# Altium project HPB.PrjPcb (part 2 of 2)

## Sheet Faults.SchDoc: MARS2 LVPS - HPB - Fault Multiplexer
size 431 x 279 mm; Organization: ORGANIZATION; Address1: APPLIED PHYSICS LAB; Address2: UNIVERSITY OF WASHINGTON; Address3: 1013 NE 40TH STREET; Address4: SEATTLE, WA 98105; DocumentNumber: 11; Revision: -; SheetNumber: 13; SheetTotal: 15; ENG_APP_DATE: --/--/--; DSN_APP_DATE: --/--/--; CHK_APP_DATE: --/--/--
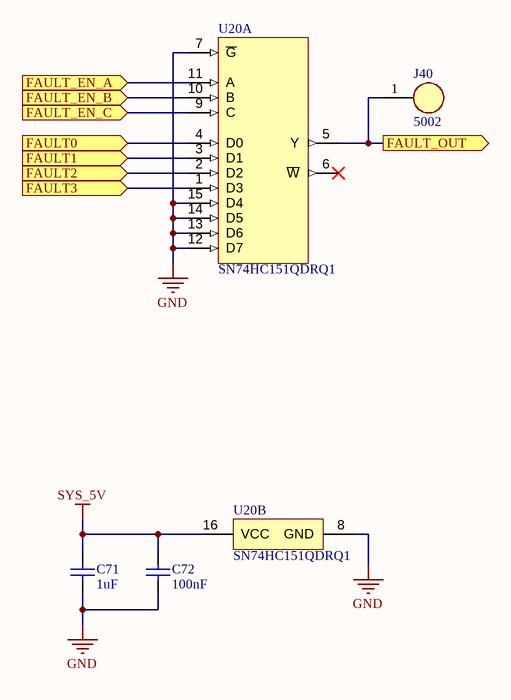
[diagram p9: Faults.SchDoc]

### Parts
C71  value 1uF  [CAPC3225X270X30ML30]  (hidden comment: Capacitor 1uF 10%, 50V, X7R, 1210)
C72  value 100nF  [CAPC1608X90X40NL10T20]  (hidden comment: Capacitor 100 nF +/-10% 50 V 0603)
J40  5002  [FP-5002-MFG]
U20  SN74HC151QDRQ1  [D0016A_M]  (parts A,B of 2)

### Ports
FAULT0 (in), FAULT1 (in), FAULT2 (in), FAULT3 (in), FAULT_EN_A (in), FAULT_EN_B (in), FAULT_EN_C (in), FAULT_OUT (out)

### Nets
GND: C71.1 C72.1 U20.7(~{G}) U20.8(GND) U20.12(D7) U20.13(D6) U20.14(D5) U20.15(D4)
SYS_5V: C71.2 C72.2 U20.16(VCC)  [project net VCC]
FAULT_MUX_A: U20.11(A) ; port FAULT_EN_A
FAULT_MUX_B: U20.10(B) ; port FAULT_EN_B
FAULT_MUX_C: U20.9(C) ; port FAULT_EN_C
FAULT_SENSE_HCB: J40.1 U20.5(Y) ; port FAULT_OUT
OUT: U20.1(D3) ; port FAULT3
OUT: U20.2(D2) ; port FAULT2  [a separate net that carries the same name]
OUT: U20.3(D1) ; port FAULT1  [a separate net that carries the same name]
OUT: U20.4(D0) ; port FAULT0  [a separate net that carries the same name]

Not connected (* = marked no-connect by the designer): U20 6(~{W})*

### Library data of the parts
C71 = CMP-001-00181-9: Chip Capacitor, 1uF, 10%, 50 V, X7R 1210 (3225 Metric); Capacitor Type: Ceramic
C72 = CMP-001-00017-14: Chip Capacitor, 100 nF, +/- 10%, 50 V, 0603 (1608 Metric); Voltage Rating: 50V; Capacitor Type: Ceramic
J40 = CMP-002-00083-3: TEST POINT PC MINI .040D WHITE; Body Material: Bronze
U20 = CMP-016-00018-2: Automotive 5-V, 8: 1 1-channel general-purpose multiplexer 16-SOIC -40 to 125; Max Supply Voltage: 6V; Bandwidth: 28MHz; Min Supply Voltage: 2V; Number of Output Lines: 1; Number of Input Lines: 8; High Level Output Current: 7.8mA; Logic Function: Multiplexer,Mux; Propagation Delay: 33ns

## Sheet Switches.SchDoc: MARS2 LVPS - HPB - PWR Switches
size 431 x 279 mm; Organization: ORGANIZATION; Address1: APPLIED PHYSICS LAB; Address2: UNIVERSITY OF WASHINGTON; Address3: 1013 NE 40TH STREET; Address4: SEATTLE, WA 98105; DocumentNumber: 8; Revision: -; SheetNumber: 9; SheetTotal: 15; ENG_APP_DATE: --/--/--; DSN_APP_DATE: --/--/--; CHK_APP_DATE: --/--/--
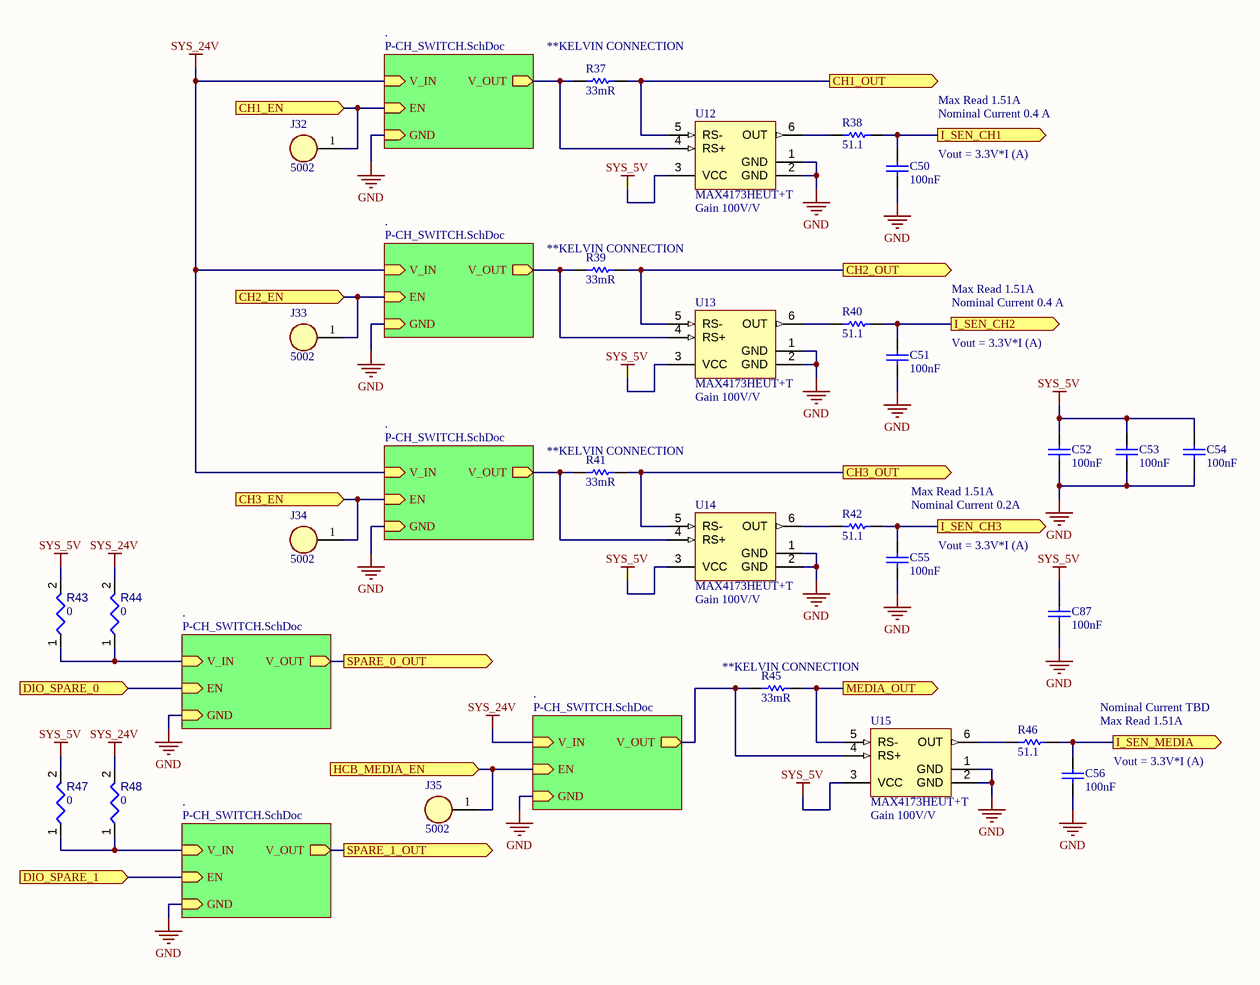
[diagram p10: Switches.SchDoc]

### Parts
C50  value 100nF  [CAPC1608X90X40NL10T20]  (hidden comment: Capacitor 100 nF +/-10% 50 V 0603)
C51  value 100nF  [CAPC1608X90X40NL10T20]  (hidden comment: Capacitor 100 nF +/-10% 50 V 0603)
C52  value 100nF  [CAPC1608X90X40NL10T20]  (hidden comment: Capacitor 100 nF +/-10% 50 V 0603)
C53  value 100nF  [CAPC1608X90X40NL10T20]  (hidden comment: Capacitor 100 nF +/-10% 50 V 0603)
C54  value 100nF  [CAPC1608X90X40NL10T20]  (hidden comment: Capacitor 100 nF +/-10% 50 V 0603)
C55  value 100nF  [CAPC1608X90X40NL10T20]  (hidden comment: Capacitor 100 nF +/-10% 50 V 0603)
C56  value 100nF  [CAPC1608X90X40NL10T20]  (hidden comment: Capacitor 100 nF +/-10% 50 V 0603)
C87  value 100nF  [CAPC1608X90X40NL10T20]  (hidden comment: Capacitor 100 nF +/-10% 50 V 0603)
J32  5002  [FP-5002-MFG]
J33  5002  [FP-5002-MFG]
J34  5002  [FP-5002-MFG]
J35  5002  [FP-5002-MFG]
R37  Resistance: 33mR  [RESC3216X70X50NL05T20]  (hidden comment: Resistor 0R033 1% 1206 1W)
R38  value 51.1  [RESC1609X50X30ML08T20]  (hidden comment: Resistor 51R1 +/-1% 0603 100 mW)
R39  Resistance: 33mR  [RESC3216X70X50NL05T20]  (hidden comment: Resistor 0R033 1% 1206 1W)
R40  value 51.1  [RESC1609X50X30ML08T20]  (hidden comment: Resistor 51R1 +/-1% 0603 100 mW)
R41  Resistance: 33mR  [RESC3216X70X50NL05T20]  (hidden comment: Resistor 0R033 1% 1206 1W)
R42  value 51.1  [RESC1609X50X30ML08T20]  (hidden comment: Resistor 51R1 +/-1% 0603 100 mW)
R43  value 0  [RESC0603(1608)_L]  (hidden comment: Jumper 0603)
R44  value 0  [RESC0603(1608)_L]  (hidden comment: Jumper 0603)
R45  Resistance: 33mR  [RESC3216X70X50NL05T20]  (hidden comment: Resistor 0R033 1% 1206 1W)
R46  value 51.1  [RESC1609X50X30ML08T20]  (hidden comment: Resistor 51R1 +/-1% 0603 100 mW)
R47  value 0  [RESC0603(1608)_L]  (hidden comment: Jumper 0603)
R48  value 0  [RESC0603(1608)_L]  (hidden comment: Jumper 0603)
U12  MAX4173HEUT+T  [MAXM-U6+1_N]
U13  MAX4173HEUT+T  [MAXM-U6+1_N]
U14  MAX4173HEUT+T  [MAXM-U6+1_N]
U15  MAX4173HEUT+T  [MAXM-U6+1_N]

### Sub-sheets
. = P-CH_SWITCH.SchDoc: V_OUT (out), V_IN (in), EN (in), GND (in)
. = P-CH_SWITCH.SchDoc: V_OUT (out), V_IN (in), EN (in), GND (in)
. = P-CH_SWITCH.SchDoc: V_OUT (out), V_IN (in), EN (in), GND (in)
. = P-CH_SWITCH.SchDoc: V_OUT (out), V_IN (in), EN (in), GND (in)
. = P-CH_SWITCH.SchDoc: V_OUT (out), V_IN (in), EN (in), GND (in)
. = P-CH_SWITCH.SchDoc: V_OUT (out), V_IN (in), EN (in), GND (in)

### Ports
CH1_EN (in), CH1_OUT (out), CH2_EN (in), CH2_OUT (out), CH3_EN (in), CH3_OUT (out), DIO_SPARE_0 (in), DIO_SPARE_1 (in), HCB_MEDIA_EN (in), I_SEN_CH1 (out), I_SEN_CH2 (out), I_SEN_CH3 (out), I_SEN_MEDIA (out), MEDIA_OUT (out), SPARE_0_OUT (out), SPARE_1_OUT (out)

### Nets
GND: C50.1 C51.1 C52.1 C53.1 C54.1 C55.1 C56.1 C87.1 U12.1(GND) U12.2(GND) U13.1(GND) U13.2(GND) U14.1(GND) U14.2(GND) U15.1(GND) U15.2(GND) ; sheet ./GND, sheet ./GND, sheet ./GND, sheet ./GND, sheet ./GND, sheet ./GND
SYS_5V: C52.2 C53.2 C54.2 C87.2 R43.2 R47.2 U12.3(VCC) U13.3(VCC) U14.3(VCC) U15.3(VCC)  [project net VCC]
SYS_24V: R44.2 R48.2 ; sheet ./V_IN, sheet ./V_IN, sheet ./V_IN, sheet ./V_IN
DIO_SPARE_0: port DIO_SPARE_0, sheet ./EN
DIO_SPARE_1: port DIO_SPARE_1, sheet ./EN
HCB_MEDIA_EN: J35.1 ; port HCB_MEDIA_EN, sheet ./EN
HPB_CISCO1_CURRENT: C50.2 R38.2 ; port I_SEN_CH1
HPB_CISCO1_EN: J32.1 ; port CH1_EN, sheet ./EN
HPB_CISCO2_CURRENT: C51.2 R40.2 ; port I_SEN_CH2
HPB_CISCO2_EN: J33.1 ; port CH2_EN, sheet ./EN
HPB_MEDIA_CURRENT: C56.2 R46.2 ; port I_SEN_MEDIA
HPB_SYNCBOX_CURRENT: C55.2 R42.2 ; port I_SEN_CH3
HPB_SYNCBOX_EN: J34.1 ; port CH3_EN, sheet ./EN
NetD1D_3: R43.1 R44.1 ; sheet ./V_IN
NetD1E_3: R47.1 R48.1 ; sheet ./V_IN
NetJ8_1: R37.1 U12.5(RS-) ; port CH1_OUT
NetJ11_1: R39.1 U13.5(RS-) ; port CH2_OUT
NetJ13_1: R41.1 U14.5(RS-) ; port CH3_OUT
NetJ15_1: R45.1 U15.5(RS-) ; port MEDIA_OUT
NetJ16_1: port SPARE_0_OUT, sheet ./V_OUT
NetJ16_2: port SPARE_1_OUT, sheet ./V_OUT
NetQ3A_4: R37.2 U12.4(RS+) ; sheet ./V_OUT
NetQ3B_4: R39.2 U13.4(RS+) ; sheet ./V_OUT
NetQ3C_4: R41.2 U14.4(RS+) ; sheet ./V_OUT
NetQ3F_4: R45.2 U15.4(RS+) ; sheet ./V_OUT
NetR38_1: R38.1 U12.6(OUT)
NetR40_1: R40.1 U13.6(OUT)
NetR42_1: R42.1 U14.6(OUT)
NetR46_1: R46.1 U15.6(OUT)

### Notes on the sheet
- (near R37) **KELVIN CONNECTION
- Nominal Current 0.4 A
- (near C50) Vout = 3.3V*I (A)
- Max Read 1.51A
- (near U12) Gain 100V/V
- (near R39) **KELVIN CONNECTION
- Vout = 3.3V*I (A)
- (near U13) Gain 100V/V
- (near R41) **KELVIN CONNECTION
- Nominal Current 0.2A
- (near U14) Gain 100V/V
- (near R45) **KELVIN CONNECTION
- Nominal Current TBD
- (near C56) Vout = 3.3V*I (A)
- (near U15) Gain 100V/V

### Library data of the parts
C50-C56 C87 = CMP-001-00017-14: as C72 on sheet Faults
J32-J35 = CMP-002-00083-3: as J40 on sheet Faults
R37 R39 R41 R45 = CMP-009-01194-1: Res Thick Film 1206 0.033 Ohm 1% 1W ±75ppm/C Pad SMD Automotive T/R; Manufacturer PN: ERJ-8CWFR033V; Temperature Coefficient: 75ppm/°C
R38 R40 R42 R46 = CMP-009-01135-1: Chip Resistor, 51.1 Ohm, +/- 1%, 0.1 W, -55 to 155 degC, 0603 (1608 Metric); Voltage Rating: 75V; Power: 100mW; Decade: 10
R43 R44 R47 R48 = CMP-009-00175-3
U12-U15 = CMP-014-00008-1: MAX4173 Series 28 V 1.2 MHz Voltage Current Sense Operational Amplifier - SOT-23; Gain: 100V/V; Common Mode Rejection Ratio: 90dB; Max Supply Voltage: 28V; -3db Bandwidth: 1.2MHz; Supply Current: 420uA; Min Supply Voltage: 3V; Input Bias Current: 700uA

## Sheet P-CH_SWITCH.SchDoc: MARS2 LVPS - HPB - P-CH Switch
size 431 x 279 mm; Organization: ORGANIZATION; Address1: APPLIED PHYSICS LAB; Address2: UNIVERSITY OF WASHINGTON; Address3: 1013 NE 40TH STREET; Address4: SEATTLE, WA 98105; DocumentNumber: 13; Revision: -; SheetNumber: 10; SheetTotal: 15; ENG_APP_DATE: --/--/--; DSN_APP_DATE: --/--/--; CHK_APP_DATE: --/--/--
Used 6 times, as channels Switches/., Switches/., Switches/., Switches/., Switches/., Switches/.. Parts and nets are listed once, with the designators drawn on the sheet.
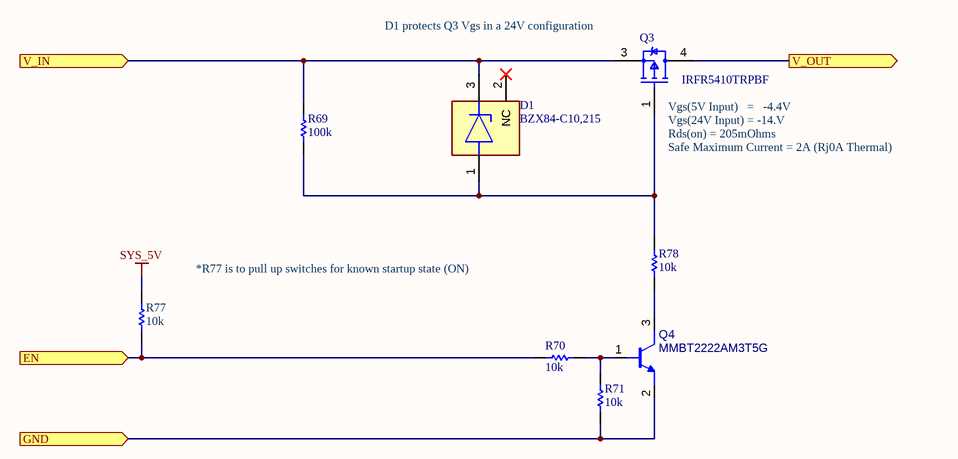
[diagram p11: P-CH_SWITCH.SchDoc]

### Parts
D1  BZX84-C10,215  [FP-SOT23-IPC_A]
Q3  IRFR5410TRPBF  [FP-PG-TO252-3-MFG]
Q4  MMBT2222AM3T5G  [ROHM-SOT723-3_V]
R69  value 100k  [RESC1608X55X25ML10T15]  (hidden comment: Resistor 100k +/-1% 0603 100 mW)
R70  value 10k  [RESC1608X55X25ML10T15]  (hidden comment: Resistor 10k +/-1% 0603 100 mW)
R71  value 10k  [RESC1608X55X25ML10T15]  (hidden comment: Resistor 10k +/-1% 0603 100 mW)
R77  value 10k  [RESC1608X55X25ML10T15]  (hidden comment: Resistor 10k +/-1% 0603 100 mW)
R78  value 10k  [RESC1608X55X25ML10T15]  (hidden comment: Resistor 10k +/-1% 0603 100 mW)

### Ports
EN (in), GND (in), V_IN (in), V_OUT (out)

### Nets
SYS_5V: R77.2
EN: R70.1 R77.1 ; port EN
GND: Q4.2(E) R71.1 ; port GND
V_IN: D1.3(K) Q3.3(S) R69.1 ; port V_IN
V_OUT: Q3.4(D) ; port V_OUT
NetD1_1: D1.1(A) Q3.1(G) R69.2 R78.2
NetQ4_1: Q4.1(B) R70.2 R71.2
NetQ4_3: Q4.3(C) R78.1

Not connected (* = marked no-connect by the designer): D1 2(NC)*

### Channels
Switches/.: designators end in A; ports EN=HPB_CISCO1_EN GND=GND V_IN=SYS_24V V_OUT=NetQ3A_4
Switches/.: designators end in B; ports EN=HPB_CISCO2_EN GND=GND V_IN=SYS_24V V_OUT=NetQ3B_4
Switches/.: designators end in C; ports EN=HPB_SYNCBOX_EN GND=GND V_IN=SYS_24V V_OUT=NetQ3C_4
Switches/.: designators end in D; ports EN=DIO_SPARE_0 GND=GND V_IN=NetD1D_3 V_OUT=NetJ16_1
Switches/.: designators end in E; ports EN=DIO_SPARE_1 GND=GND V_IN=NetD1E_3 V_OUT=NetJ16_2
Switches/.: designators end in F; ports EN=HCB_MEDIA_EN GND=GND V_IN=SYS_24V V_OUT=NetQ3F_4

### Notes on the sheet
- (near Q3) D1 protects Q3 Vgs in a 24V configuration
- (near Q3) Vgs(5V Input)   =   -4.4V
- (near Q3) Vgs(24V Input) = -14.V
- (near Q3) Rds(on) = 205mOhms
- Safe Maximum Current = 2A (Rj0A Thermal)
- *R77 is to pull up switches for known startup state (ON)

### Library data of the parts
D1 = CMP-004-00069-1: Diode Zener Single 10 Volt 5% 250m Watt Automotive 3-Pin SOT-23
Q3 = CMP-013-00042-2: MOSFET P-CH 100V 13A DPAK; Gate to Source Voltage (Vgs): 20V; Drain to Source Resistance: 205mR; Max Dual Supply Voltage: -100V; Polarization: P; Power Dissipation: 66W; Threshold Voltage: -4V; Input Capacitance: 760pF; Turn-On Delay Time: 15ns; Turn-Off Delay Time: 45ns; Rise Time: 58ns; Transistor Type: PMOS
Q4 = CMP-013-00028-3: NPN General Purpose Transistor, 3-Pin SOT-723, Pb-Free, Tape and Reel
R69 = CMP-009-00023-6: Chip Resistor, 100 KOhm, +/- 1%, 0.1 W, -55 to 155 degC, 0603 (1608 Metric); Voltage Rating: 50V; Power: 100mW
R70 R71 R77 R78 = CMP-009-00017-7: Chip Resistor, 10 KOhm, +/- 1%, 01 W, -55 to 155 degC, 0603 (1608 Metric); Voltage Rating: 50V; Power: 100mW

## Sheet RS232 Isolator.SchDoc: MARS2 LVPS - HPB - RS232 Isolator
size 431 x 279 mm; Organization: ORGANIZATION; Address1: APPLIED PHYSICS LAB; Address2: UNIVERSITY OF WASHINGTON; Address3: 1013 NE 40TH STREET; Address4: SEATTLE, WA 98105; DocumentNumber: 9; Revision: -; SheetNumber: 11; SheetTotal: 15; ENG_APP_DATE: --/--/--; DSN_APP_DATE: --/--/--; CHK_APP_DATE: --/--/--
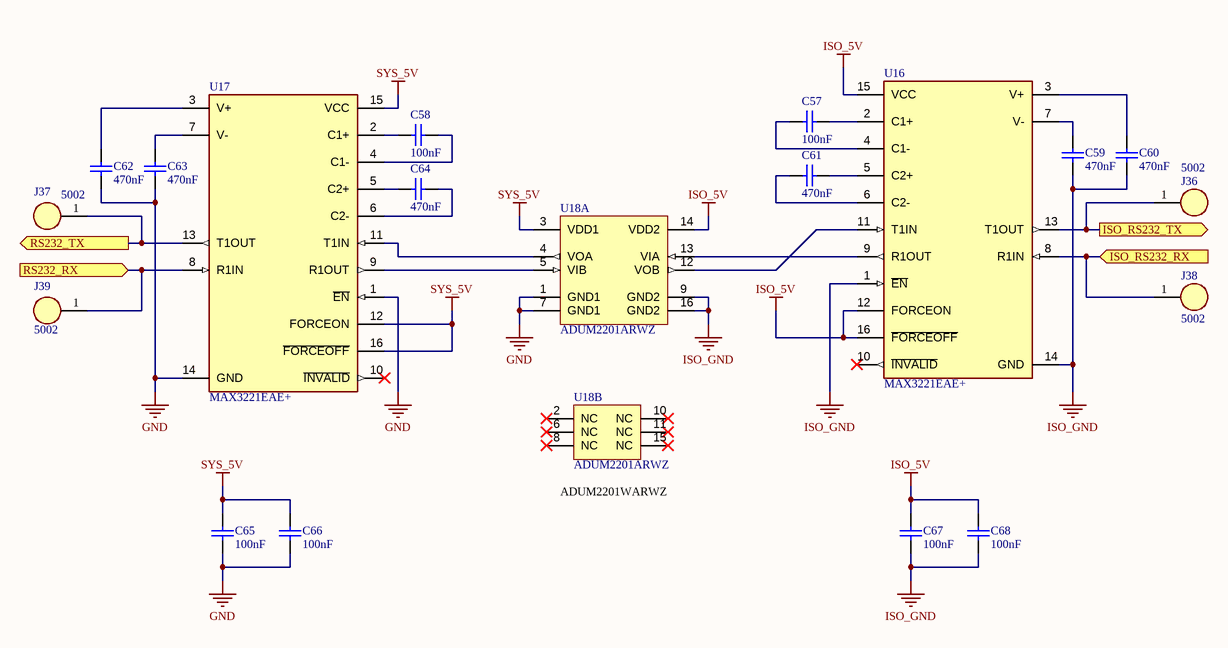
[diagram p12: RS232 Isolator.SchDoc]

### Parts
C57  value 100nF  [CAPC1608X90X40NL10T20]  (hidden comment: Capacitor 100 nF +/-10% 50 V 0603)
C58  value 100nF  [CAPC1608X90X40NL10T20]  (hidden comment: Capacitor 100 nF +/-10% 50 V 0603)
C59  value 470nF  [CAPC0603(1608)100_L]  (hidden comment: Capacitor 470nF +/-20% 25V 0603)
C60  value 470nF  [CAPC0603(1608)100_L]  (hidden comment: Capacitor 470nF +/-20% 25V 0603)
C61  value 470nF  [CAPC0603(1608)100_L]  (hidden comment: Capacitor 470nF +/-20% 25V 0603)
C62  value 470nF  [CAPC0603(1608)100_L]  (hidden comment: Capacitor 470nF +/-20% 25V 0603)
C63  value 470nF  [CAPC0603(1608)100_L]  (hidden comment: Capacitor 470nF +/-20% 25V 0603)
C64  value 470nF  [CAPC0603(1608)100_L]  (hidden comment: Capacitor 470nF +/-20% 25V 0603)
C65  value 100nF  [CAPC1608X90X40NL10T20]  (hidden comment: Capacitor 100 nF +/-10% 50 V 0603)
C66  value 100nF  [CAPC1608X90X40NL10T20]  (hidden comment: Capacitor 100 nF +/-10% 50 V 0603)
C67  value 100nF  [CAPC1608X90X40NL10T20]  (hidden comment: Capacitor 100 nF +/-10% 50 V 0603)
C68  value 100nF  [CAPC1608X90X40NL10T20]  (hidden comment: Capacitor 100 nF +/-10% 50 V 0603)
J36  5002  [FP-5002-MFG]
J37  5002  [FP-5002-MFG]
J38  5002  [FP-5002-MFG]
J39  5002  [FP-5002-MFG]
U16  MAX3221EAE+  [FP-A16-2-IPC_C]
U17  MAX3221EAE+  [FP-A16-2-IPC_C]
U18  ADUM2201ARWZ  [ADI-RW-16_M]  (parts A,B of 2)

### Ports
ISO_RS232_RX (in), ISO_RS232_TX (out), RS232_RX (in), RS232_TX (out)

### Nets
GND: C62.1 C63.1 C65.1 C66.1 U17.1(~{EN}) U17.14(GND) U18.1(GND1) U18.7(GND1)
ISO_5V: C67.2 C68.2 U16.12(FORCEON) U16.15(VCC) U16.16(~{FORCEOFF}) U18.14(VDD2)
ISO_GND: C59.1 C60.1 C67.1 C68.1 U16.1(~{EN}) U16.14(GND) U18.9(GND2) U18.16(GND2)
SYS_5V: C65.2 C66.2 U17.12(FORCEON) U17.15(VCC) U17.16(~{FORCEOFF}) U18.3(VDD1)  [project net VCC]
NetC57_1: C57.1 U16.2(C1+)
NetC57_2: C57.2 U16.4(C1-)
NetC58_1: C58.1 U17.4(C1-)
NetC58_2: C58.2 U17.2(C1+)
NetC59_2: C59.2 U16.7(V-)
NetC60_2: C60.2 U16.3(V+)
NetC61_1: C61.1 U16.6(C2-)
NetC61_2: C61.2 U16.5(C2+)
NetC62_2: C62.2 U17.3(V+)
NetC63_2: C63.2 U17.7(V-)
NetC64_1: C64.1 U17.5(C2+)
NetC64_2: C64.2 U17.6(C2-)
NetJ5_3: J38.1 U16.8(R1IN) ; port ISO_RS232_RX
NetJ5_6: J36.1 U16.13(T1OUT) ; port ISO_RS232_TX
NetJ6_1: J39.1 U17.8(R1IN) ; port RS232_RX
NetJ6_3: J37.1 U17.13(T1OUT) ; port RS232_TX
NetU16_9: U16.9(R1OUT) U18.13(VIA)
NetU16_11: U16.11(T1IN) U18.12(VOB)
NetU17_9: U17.9(R1OUT) U18.5(VIB)
NetU17_11: U17.11(T1IN) U18.4(VOA)

Not connected (* = marked no-connect by the designer): U16 10(~{INVALID})*; U17 10(~{INVALID})*; U18 2(NC)* 6(NC)* 8(NC)* 10(NC)* 11(NC)* 15(NC)*

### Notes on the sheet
- (near U18) ADUM2201WARWZ

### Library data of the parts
C57 C58 C65-C68 = CMP-001-00017-14: as C72 on sheet Faults
C59-C64 = CMP-001-00077-11: Chip Capacitor, 470nF +/-20%, 25V, 0603, Thickness 1 mm; Capacitor Type: Ceramic; Tolerance: 10%; Decade: 100nF
J36-J39 = CMP-002-00083-3: as J40 on sheet Faults
U16 U17 = CMP-015-00011-1: MAX3221 Series 235 kbps 5.5 V Surface Mount RS-232 Transceiver - SSOP-16
U18 = CMP-015-00014-3: 5000Vrms 25kV/us 1Mbps Digital Isolation RS232,TTL RS485; Min Supply Voltage: 3V; Isolated Power: No; Nominal Supply Current: 800uA; Propagation Delay: 150ns; Data Rate: 10Mbps; Pulse Width Distortion (PWD): 40ns; Max Supply Voltage: 5.5V; Rise Time: 1ms; Max Input Current: 10uA; Number of Channels: 2

## Sheet Temperature.SchDoc: MARS2 LVPS - HPB - Temp Sensors
size 431 x 279 mm; Organization: ORGANIZATION; Address1: APPLIED PHYSICS LAB; Address2: UNIVERSITY OF WASHINGTON; Address3: 1013 NE 40TH STREET; Address4: SEATTLE, WA 98105; DocumentNumber: 12; Revision: -; SheetNumber: 14; SheetTotal: 15; ENG_APP_DATE: --/--/--; DSN_APP_DATE: --/--/--; CHK_APP_DATE: --/--/--
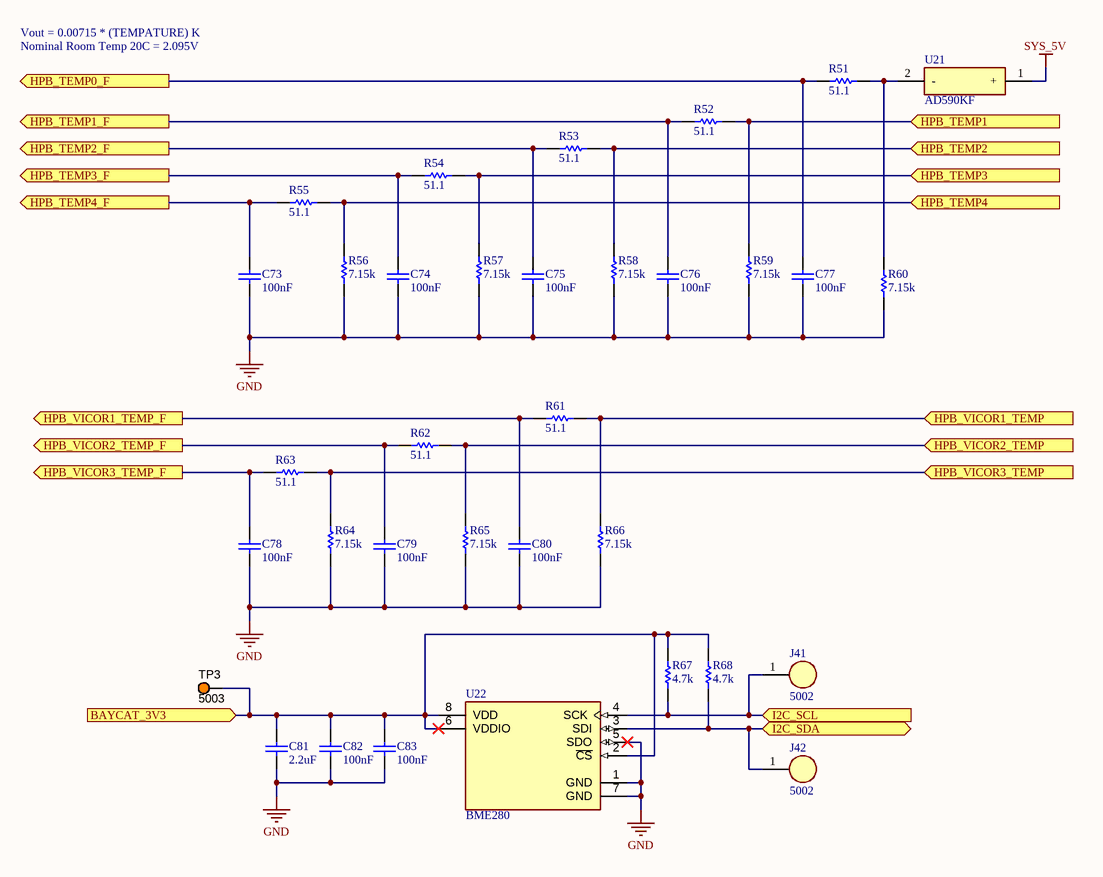
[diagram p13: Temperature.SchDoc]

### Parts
C73  value 100nF  [CAPC1608X90X40NL10T20]  (hidden comment: Capacitor 100 nF +/-10% 50 V 0603)
C74  value 100nF  [CAPC1608X90X40NL10T20]  (hidden comment: Capacitor 100 nF +/-10% 50 V 0603)
C75  value 100nF  [CAPC1608X90X40NL10T20]  (hidden comment: Capacitor 100 nF +/-10% 50 V 0603)
C76  value 100nF  [CAPC1608X90X40NL10T20]  (hidden comment: Capacitor 100 nF +/-10% 50 V 0603)
C77  value 100nF  [CAPC1608X90X40NL10T20]  (hidden comment: Capacitor 100 nF +/-10% 50 V 0603)
C78  value 100nF  [CAPC1608X90X40NL10T20]  (hidden comment: Capacitor 100 nF +/-10% 50 V 0603)
C79  value 100nF  [CAPC1608X90X40NL10T20]  (hidden comment: Capacitor 100 nF +/-10% 50 V 0603)
C80  value 100nF  [CAPC1608X90X40NL10T20]  (hidden comment: Capacitor 100 nF +/-10% 50 V 0603)
C81  value 2.2uF  [CAPC2013X95X50ML10T25]  (hidden comment: Capacitor 2.2uF 10%, 50V, X7R, 0805)
C82  value 100nF  [CAPC1608X90X40NL10T20]  (hidden comment: Capacitor 100 nF +/-10% 50 V 0603)
C83  value 100nF  [CAPC1608X90X40NL10T20]  (hidden comment: Capacitor 100 nF +/-10% 50 V 0603)
J41  5002  [FP-5002-MFG]
J42  5002  [FP-5002-MFG]
R51  value 51.1  [RESC1609X50X30ML08T20]  (hidden comment: Resistor 51R1 +/-1% 0603 100 mW)
R52  value 51.1  [RESC1609X50X30ML08T20]  (hidden comment: Resistor 51R1 +/-1% 0603 100 mW)
R53  value 51.1  [RESC1609X50X30ML08T20]  (hidden comment: Resistor 51R1 +/-1% 0603 100 mW)
R54  value 51.1  [RESC1609X50X30ML08T20]  (hidden comment: Resistor 51R1 +/-1% 0603 100 mW)
R55  value 51.1  [RESC1609X50X30ML08T20]  (hidden comment: Resistor 51R1 +/-1% 0603 100 mW)
R56  value 7.15k  [RESC1609X50X30ML08T20]  (hidden comment: Resistor 7K15 +/-1% 0603 100 mW)
R57  value 7.15k  [RESC1609X50X30ML08T20]  (hidden comment: Resistor 7K15 +/-1% 0603 100 mW)
R58  value 7.15k  [RESC1609X50X30ML08T20]  (hidden comment: Resistor 7K15 +/-1% 0603 100 mW)
R59  value 7.15k  [RESC1609X50X30ML08T20]  (hidden comment: Resistor 7K15 +/-1% 0603 100 mW)
R60  value 7.15k  [RESC1609X50X30ML08T20]  (hidden comment: Resistor 7K15 +/-1% 0603 100 mW)
R61  value 51.1  [RESC1609X50X30ML08T20]  (hidden comment: Resistor 51R1 +/-1% 0603 100 mW)
R62  value 51.1  [RESC1609X50X30ML08T20]  (hidden comment: Resistor 51R1 +/-1% 0603 100 mW)
R63  value 51.1  [RESC1609X50X30ML08T20]  (hidden comment: Resistor 51R1 +/-1% 0603 100 mW)
R64  value 7.15k  [RESC1609X50X30ML08T20]  (hidden comment: Resistor 7K15 +/-1% 0603 100 mW)
R65  value 7.15k  [RESC1609X50X30ML08T20]  (hidden comment: Resistor 7K15 +/-1% 0603 100 mW)
R66  value 7.15k  [RESC1609X50X30ML08T20]  (hidden comment: Resistor 7K15 +/-1% 0603 100 mW)
R67  value 4.7k  [RESC1608X55X25ML10T15]  (hidden comment: Resistor 4k7 +/-1% 0603 100 mW)
R68  value 4.7k  [RESC1608X55X25ML10T15]  (hidden comment: Resistor 4k7 +/-1% 0603 100 mW)
TP3  5003  [KSTN-5003]
U21  AD590KF  [FP-F-2-MFG]
U22  BME280  [FP-BME280-MFG]

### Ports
BAYCAT_3V3 (in), HPB_TEMP0_F (out), HPB_TEMP1 (in), HPB_TEMP1_F (out), HPB_TEMP2 (in), HPB_TEMP2_F (out), HPB_TEMP3 (in), HPB_TEMP3_F (out), HPB_TEMP4 (in), HPB_TEMP4_F (out), HPB_VICOR1_TEMP (in), HPB_VICOR1_TEMP_F (out), HPB_VICOR2_TEMP (in), HPB_VICOR2_TEMP_F (out), HPB_VICOR3_TEMP (in), HPB_VICOR3_TEMP_F (out), I2C_SCL (in), I2C_SDA (bidir)

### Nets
GND: C73.1 C74.1 C75.1 C76.1 C77.1 C78.1 C79.1 C80.1 C81.1 C82.1 C83.1 R56.1 R57.1 R58.1 R59.1 R60.1 R64.1 R65.1 R66.1 U22.1(GND) U22.5(SDO) U22.7(GND)
SYS_5V: U21.1(+)  [project net VCC]
BAYCAT_3V3: C81.2 C82.2 C83.2 R67.2 R68.2 TP3.1 U22.2(~{CS}) U22.6(VDDIO) U22.8(VDD) ; port BAYCAT_3V3
HPB_TEMP0: C77.2 R51.1 ; port HPB_TEMP0_F
HPB_TEMP1: C76.2 R52.1 ; port HPB_TEMP1_F
HPB_TEMP2: C75.2 R53.1 ; port HPB_TEMP2_F
HPB_TEMP3: C74.2 R54.1 ; port HPB_TEMP3_F
HPB_TEMP4: C73.2 R55.1 ; port HPB_TEMP4_F
HPB_VICOR1_TEMP: C80.2 R61.1 ; port HPB_VICOR1_TEMP_F
HPB_VICOR2_TEMP: C79.2 R62.1 ; port HPB_VICOR2_TEMP_F
HPB_VICOR3_TEMP: C78.2 R63.1 ; port HPB_VICOR3_TEMP_F
I2C_SCL: J41.1 R67.1 U22.4(SCK) ; port I2C_SCL
I2C_SDA: J42.1 R68.1 U22.3(SDI) ; port I2C_SDA
NetJ10_1: R61.2 R66.2 ; port HPB_VICOR1_TEMP
NetJ10_2: R62.2 R65.2 ; port HPB_VICOR2_TEMP
NetJ10_3: R63.2 R64.2 ; port HPB_VICOR3_TEMP
NetJ10_4: R52.2 R59.2 ; port HPB_TEMP1
NetJ10_5: R53.2 R58.2 ; port HPB_TEMP2
NetJ10_6: R54.2 R57.2 ; port HPB_TEMP3
NetJ10_7: R55.2 R56.2 ; port HPB_TEMP4
NetR51_2: R51.2 R60.2 U21.2(-)

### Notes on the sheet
- Vout = 0.00715 * (TEMPATURE) K
- Nominal Room Temp 20C = 2.095V

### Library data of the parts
C73-C80 C82 C83 = CMP-001-00017-14: as C72 on sheet Faults
C81 = CMP-001-00167-10: Chip Capacitor, 2.2uF, 10%, 50 V, X7R 0805 (2012 Metric); Decade: 1uF; Capacitor Type: Ceramic
J41 J42 = CMP-002-00083-3: as J40 on sheet Faults
R51-R55 R61-R63 = CMP-009-01135-1: as R38 on sheet Switches
R56-R60 R64-R66 = CMP-009-00865-4: Chip Resistor, 7.15k Ohm, +/- 1%, 0.1 W, -55 to 155 degC, 0603 (1608 Metric); Voltage Rating: 75V; Power: 100mW; Decade: 1k
R67 R68 = CMP-009-00031-7: Chip Resistor, 4.7 KOhm, +/- 1%, 0.1 W, -55 to 155 degC, 0603 (1608 Metric); Decade: 1k; Power: 100mW
TP3 = CMP-002-00037-2: Test Point, Orange, Height 4.6 mm, Tail Length 3 mm, 1-Pin THD, RoHS; Manufacturer: Keystone
U21 = CMP-010-00024-2: SENSOR ANALOG -55C-150C 2FLATPK / Two-Twrminal IC Temperature Transducer; Max Supply Voltage: 30V; Min Supply Voltage: 4V; Forward Voltage: 44V; Output Current: 298.2uA
U22 = CMP-010-00027-1: SENSOR PRESSURE HUMIDITY TEMP; Sensor Type: Temperature; Output Type: SPI,I2C; Accuracy: 3%; Response Time: 1s

## Sheet I2C_GPIO.SchDoc: MARS2 LVPS - HPB - I2C GPIO
size 431 x 279 mm; Organization: ORGANIZATION; Address1: APPLIED PHYSICS LAB; Address2: UNIVERSITY OF WASHINGTON; Address3: 1013 NE 40TH STREET; Address4: SEATTLE, WA 98105; DocumentNumber: 14; Revision: -; SheetNumber: 15; SheetTotal: 15; ENG_APP_DATE: --/--/--; DSN_APP_DATE: --/--/--; CHK_APP_DATE: --/--/--
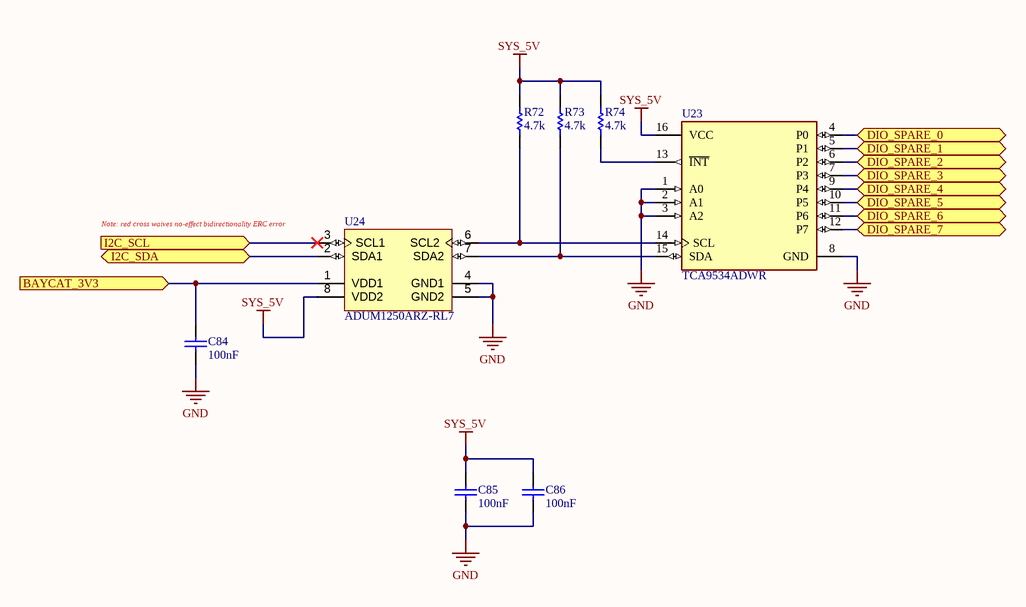
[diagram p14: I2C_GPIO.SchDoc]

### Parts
C84  value 100nF  [CAPC1608X90X40NL10T20]  (hidden comment: Capacitor 100 nF +/-10% 50 V 0603)
C85  value 100nF  [CAPC1608X90X40NL10T20]  (hidden comment: Capacitor 100 nF +/-10% 50 V 0603)
C86  value 100nF  [CAPC1608X90X40NL10T20]  (hidden comment: Capacitor 100 nF +/-10% 50 V 0603)
R72  value 4.7k  [RESC1608X55X25ML10T15]  (hidden comment: Resistor 4k7 +/-1% 0603 100 mW)
R73  value 4.7k  [RESC1608X55X25ML10T15]  (hidden comment: Resistor 4k7 +/-1% 0603 100 mW)
R74  value 4.7k  [RESC1608X55X25ML10T15]  (hidden comment: Resistor 4k7 +/-1% 0603 100 mW)
U23  TCA9534ADWR  [FP-DW0016A-IPC_C]
U24  ADUM1250ARZ-RL7  [ADI-R-8_N]

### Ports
BAYCAT_3V3 (in), DIO_SPARE_0 (bidir), DIO_SPARE_1 (bidir), DIO_SPARE_2 (bidir), DIO_SPARE_3 (bidir), DIO_SPARE_4 (bidir), DIO_SPARE_5 (bidir), DIO_SPARE_6 (bidir), DIO_SPARE_7 (bidir), I2C_SCL (in), I2C_SDA (bidir)

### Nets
GND: C84.1 C85.1 C86.1 U23.1(A0) U23.2(A1) U23.3(A2) U23.8(GND) U24.4(GND1) U24.5(GND2)
SYS_5V: C85.2 C86.2 R72.2 R73.2 R74.2 U23.16(VCC) U24.8(VDD2)  [project net VCC]
BAYCAT_3V3: C84.2 U24.1(VDD1) ; port BAYCAT_3V3
DIO_SPARE_0: U23.4(P0) ; port DIO_SPARE_0
DIO_SPARE_1: U23.5(P1) ; port DIO_SPARE_1
DIO_SPARE_2: U23.6(P2) ; port DIO_SPARE_2
DIO_SPARE_3: U23.7(P3) ; port DIO_SPARE_3
DIO_SPARE_4: U23.9(P4) ; port DIO_SPARE_4
DIO_SPARE_5: U23.10(P5) ; port DIO_SPARE_5
DIO_SPARE_6: U23.11(P6) ; port DIO_SPARE_6
DIO_SPARE_7: U23.12(P7) ; port DIO_SPARE_7
I2C_SCL: U24.3(SCL1) ; port I2C_SCL
I2C_SDA: U24.2(SDA1) ; port I2C_SDA
NetR72_1: R72.1 U23.14(SCL) U24.6(SCL2)
NetR73_1: R73.1 U23.15(SDA) U24.7(SDA2)
NetR74_1: R74.1 U23.13(~{INT})

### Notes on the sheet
- (near U24) Note: red cross waives no-effect bidirectionality ERC error

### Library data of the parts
C84-C86 = CMP-001-00017-14: as C72 on sheet Faults
R72-R74 = CMP-009-00031-7: as R67 on sheet Temperature
U23 = CMP-015-00015-1: 8-bit 1.65- to 5.5-V I2C/SMBus I/O expander with interrupt, & config registers 16-SOIC -40 to 85; Output Type: PUSH-PULL; Interface: I2C; Number of I/Os: 8; Frequency: 400kHz
U24 = CMP-024-00005-1: I²C Digital Isolator 2500Vrms 2 Channel 1Mbps 25kV/µs CMTI 8-SOIC (0.154, 3.90mm Width); Number of Channels: 2; Channel Type: Bidirectional; Operating Supply Voltage: 5V; Pulse Width Distortion (PWD): 85ns; Supply Current: 5mA; Min Supply Voltage: 3V; Max Supply Voltage: 5.5V; Propagation Delay: 150ns; Number of Input Lines: 1

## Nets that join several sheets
GND: 24V Power Bus Supply (26 pins), 24V Bus Power Supply/1.024V Comparator V1-Left (7 pins), 24V Bus Power Supply/1.024V Comparator V2-Left (7 pins), 24V Bus Power Supply/1.024V Comparator V1-Right (7 pins), 24V Bus Power Supply/1.024V Comparator V2-Right (7 pins), Mezzanine Connector (33 pins), 24V Isolation (6 pins), 5V_POWER_SUPPLY (17 pins), Output Connectors (28 pins), Faults (8 pins), Switches (16 pins), Switches/. (Q4A.2 R71A.1), Switches/. (Q4B.2 R71B.1), Switches/. (Q4C.2 R71C.1), Switches/. (Q4D.2 R71D.1), Switches/. (Q4E.2 R71E.1), Switches/. (Q4F.2 R71F.1), RS232 Isolator (8 pins), Temperature (22 pins), I2C_GPIO (9 pins)
ISO_5V: 24V Isolation (J31.1 U9.3), RS232 Isolator (6 pins)
ISO_24V: 24V Isolation (7 pins), MVC Connector (J5.1 J5.2)
ISO_GND: 24V Isolation (10 pins), MVC Connector (J5.4 J5.5), RS232 Isolator (8 pins)
SYS_24V: 24V Power Bus Supply (R19.2 R20.2 TP1.1 U6.5), Mezzanine Connector (5 pins), 24V Isolation (R26.2 U8.4), 5V_POWER_SUPPLY (C43.2 L3.1), Output Connectors (R49.1 U19.4), Switches (R44.2 R48.2), Switches/. (D1A.3 Q3A.3 R69A.1), Switches/. (D1B.3 Q3B.3 R69B.1), Switches/. (D1C.3 Q3C.3 R69C.1), Switches/. (D1F.3 Q3F.3 R69F.1)
VCC: 24V Power Bus Supply (C13.2 U6.3), 24V Bus Power Supply/1.024V Comparator V1-Left (5 pins), 24V Bus Power Supply/1.024V Comparator V2-Left (5 pins), 24V Bus Power Supply/1.024V Comparator V1-Right (5 pins), 24V Bus Power Supply/1.024V Comparator V2-Right (5 pins), 24V Isolation (C38.2 U8.3), 5V_POWER_SUPPLY (6 pins), Output Connectors (13 pins), Faults (C71.2 C72.2 U20.16), Switches (10 pins), Switches/. (R77A.2), Switches/. (R77B.2), Switches/. (R77C.2), Switches/. (R77D.2), Switches/. (R77E.2), Switches/. (R77F.2), RS232 Isolator (6 pins), Temperature (U21.1), I2C_GPIO (7 pins)
24V_UNSWCH_BUS_CURRENT: Mezzanine Connector (J2.18), Output Connectors (C69.2 R50.2)
BAYCAT_3V3: Mezzanine Connector (J1.18), Temperature (9 pins), I2C_GPIO (C84.2 U24.1)
DIO_SPARE_0: Mezzanine Connector (J1.2), Switches/. (R70D.1 R77D.1), I2C_GPIO (U23.4)
DIO_SPARE_1: Mezzanine Connector (J1.4), Switches/. (R70E.1 R77E.1), I2C_GPIO (U23.5)
DIO_SPARE_2: Mezzanine Connector (J1.6), I2C_GPIO (U23.6)
DIO_SPARE_3: Mezzanine Connector (J1.8), I2C_GPIO (U23.7)
DIO_SPARE_4: Mezzanine Connector (J1.10), I2C_GPIO (U23.9)
DIO_SPARE_5: Mezzanine Connector (J1.12), I2C_GPIO (U23.10)
DIO_SPARE_6: Mezzanine Connector (J1.14), I2C_GPIO (U23.11)
DIO_SPARE_7: Mezzanine Connector (J1.16), I2C_GPIO (U23.12)
FAULT_MUX_A: Mezzanine Connector (J2.58), Faults (U20.11)
FAULT_MUX_B: Mezzanine Connector (J2.60), Faults (U20.10)
FAULT_MUX_C: Mezzanine Connector (J2.62), Faults (U20.9)
FAULT_SENSE_HCB: Mezzanine Connector (J2.55), Faults (J40.1 U20.5)
HCB_MEDIA_EN: Mezzanine Connector (J1.30), Switches (J35.1), Switches/. (R70F.1 R77F.1)
HPB_5V_CURRENT: Mezzanine Connector (J2.34), 5V_POWER_SUPPLY (C45.2 R34.2)
HPB_5V_VOLTAGE: Mezzanine Connector (J2.30), 5V_POWER_SUPPLY (C46.2 R35.2)
HPB_24V_CURRENT: 24V Power Bus Supply (C24.2 R22.2), Mezzanine Connector (J2.26)
HPB_24V_VOLTAGE: 24V Power Bus Supply (C25.2 R23.2), Mezzanine Connector (J2.22)
HPB_CISCO1_CURRENT: Mezzanine Connector (J2.2), Switches (C50.2 R38.2)
HPB_CISCO1_EN: Mezzanine Connector (J1.49), Switches (J32.1), Switches/. (R70A.1 R77A.1)
HPB_CISCO2_CURRENT: Mezzanine Connector (J2.6), Switches (C51.2 R40.2)
HPB_CISCO2_EN: Mezzanine Connector (J1.51), Switches (J33.1), Switches/. (R70B.1 R77B.1)
HPB_ISO24V_CURRENT: Mezzanine Connector (J2.14), 24V Isolation (C37.2 R28.2)
HPB_MEDIA_CURRENT: Mezzanine Connector (J2.64), Switches (C56.2 R46.2)
HPB_SYNCBOX_CURRENT: Mezzanine Connector (J2.10), Switches (C55.2 R42.2)
HPB_SYNCBOX_EN: Mezzanine Connector (J1.53), Switches (J34.1), Switches/. (R70C.1 R77C.1)
HPB_TEMP0: Mezzanine Connector (J1.44), Temperature (C77.2 R51.1)
HPB_TEMP1: Mezzanine Connector (J1.46), Temperature (C76.2 R52.1)
HPB_TEMP2: Mezzanine Connector (J1.48), Temperature (C75.2 R53.1)
HPB_TEMP3: Mezzanine Connector (J1.50), Temperature (C74.2 R54.1)
HPB_TEMP4: Mezzanine Connector (J1.52), Temperature (C73.2 R55.1)
HPB_VICOR1_TEMP: Mezzanine Connector (J1.38), Temperature (C80.2 R61.1)
HPB_VICOR2_TEMP: Mezzanine Connector (J1.40), Temperature (C79.2 R62.1)
HPB_VICOR3_TEMP: Mezzanine Connector (J1.42), Temperature (C78.2 R63.1)
I2C_SCL: Mezzanine Connector (J1.26), Temperature (J41.1 R67.1 U22.4), I2C_GPIO (U24.3)
I2C_SDA: Mezzanine Connector (J1.22), Temperature (J42.1 R68.1 U22.3), I2C_GPIO (U24.2)
N187_L: IGB Power Connector (J3.B J20.1), 24V Power Bus Supply (8 pins)
N187_R: IGB Power Connector (J4.B J22.1), 24V Power Bus Supply (8 pins)
NetD1D_3: Switches (R43.1 R44.1), Switches/. (D1D.3 Q3D.3 R69D.1)
NetD1E_3: Switches (R47.1 R48.1), Switches/. (D1E.3 Q3E.3 R69E.1)
NetJ5_3: MVC Connector (J5.3), RS232 Isolator (J38.1 U16.8)
NetJ5_6: MVC Connector (J5.6), RS232 Isolator (J36.1 U16.13)
NetJ6_1: Output Connectors (J6.1), RS232 Isolator (J39.1 U17.8)
NetJ6_3: Output Connectors (J6.3), RS232 Isolator (J37.1 U17.13)
NetJ8_1: Output Connectors (J8.1 J8.2), Switches (R37.1 U12.5)
NetJ10_1: Output Connectors (J10.1), Temperature (R61.2 R66.2)
NetJ10_2: Output Connectors (J10.2), Temperature (R62.2 R65.2)
NetJ10_3: Output Connectors (J10.3), Temperature (R63.2 R64.2)
NetJ10_4: Output Connectors (J10.4), Temperature (R52.2 R59.2)
NetJ10_5: Output Connectors (J10.5), Temperature (R53.2 R58.2)
NetJ10_6: Output Connectors (J10.6), Temperature (R54.2 R57.2)
NetJ10_7: Output Connectors (J10.7), Temperature (R55.2 R56.2)
NetJ11_1: Output Connectors (J11.1 J11.2), Switches (R39.1 U13.5)
NetJ13_1: Output Connectors (J13.1 J13.2), Switches (R41.1 U14.5)
NetJ15_1: Output Connectors (J15.1 J15.2), Switches (R45.1 U15.5)
NetJ16_1: Output Connectors (J16.1), Switches/. (Q3D.4)
NetJ16_2: Output Connectors (J16.2), Switches/. (Q3E.4)
NetQ3A_4: Switches (R37.2 U12.4), Switches/. (Q3A.4)
NetQ3B_4: Switches (R39.2 U13.4), Switches/. (Q3B.4)
NetQ3C_4: Switches (R41.2 U14.4), Switches/. (Q3C.4)
NetQ3F_4: Switches (R45.2 U15.4), Switches/. (Q3F.4)
OUT: 24V Bus Power Supply/1.024V Comparator V1-Left (U2A.1), Faults (U20.1)
OUT: 24V Bus Power Supply/1.024V Comparator V2-Left (U2B.1), Faults (U20.2)
OUT: 24V Bus Power Supply/1.024V Comparator V1-Right (U2C.1), Faults (U20.3)
OUT: 24V Bus Power Supply/1.024V Comparator V2-Right (U2D.1), Faults (U20.4)
P187_L: IGB Power Connector (J3.A J19.1), 24V Power Bus Supply (6 pins)
P187_R: IGB Power Connector (J4.A J21.1), 24V Power Bus Supply (6 pins)
V1_L_S: 24V Power Bus Supply (DC1.6 J24.1 R11.1), 24V Bus Power Supply/1.024V Comparator V1-Left (U2A.3)
V1_R_S: 24V Power Bus Supply (DC3.6 J27.1 R21.1), 24V Bus Power Supply/1.024V Comparator V1-Right (U2C.3)
V2_L_S: 24V Power Bus Supply (DC2.6 J25.1 R16.1), 24V Bus Power Supply/1.024V Comparator V2-Left (U2B.3)
V2_R_S: 24V Power Bus Supply (DC4.6 J28.1 R25.1), 24V Bus Power Supply/1.024V Comparator V2-Right (U2D.3)

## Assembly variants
MAIN: not fitted C911.024V Comparator V1-Left C911.024V Comparator V1-Right C911.024V Comparator V2-Left C911.024V Comparator V2-Right R11 R15 R16 R18 R21 R25 R27 R29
